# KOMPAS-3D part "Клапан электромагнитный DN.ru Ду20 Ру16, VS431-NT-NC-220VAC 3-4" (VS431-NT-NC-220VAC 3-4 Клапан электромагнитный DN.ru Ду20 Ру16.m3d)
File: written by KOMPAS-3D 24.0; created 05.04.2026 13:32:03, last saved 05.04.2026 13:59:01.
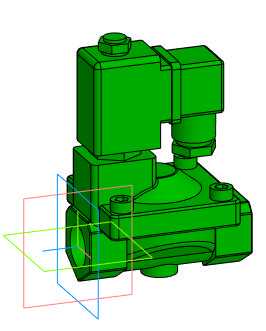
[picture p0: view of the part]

Document properties: Автор: artio; Полное имя файла: C:\Users\artio\OneDrive\Рабочий стол\Клапан электромагнитный DN.ru\VS431\VS431-NT-NC\VS431-NT-NC-220VAC\Ду20\VS431-NT-NC-220VAC 3-4 Клапан электромагнитный DN.ru Ду20 Ру16.m3d

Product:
- Body: Тело 1  | qty 1
    Масса: 1.198355
- Part/product: Клапан электромагнитный DN.ru Ду20 Ру16  | designation VS431-NT-NC-220VAC 3-4
    Масса: 0.907
    Раздел спецификации: Прочие изделия
    Примечание: D130-04669
    additional columns: ef56311e-7521-43dc-8291-0e6108b3d81d; artio; c; Шероховатость не задана; Да

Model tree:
1. Операция без истории:1

Expressions: VS431-NT-NC-220VAC 3-4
